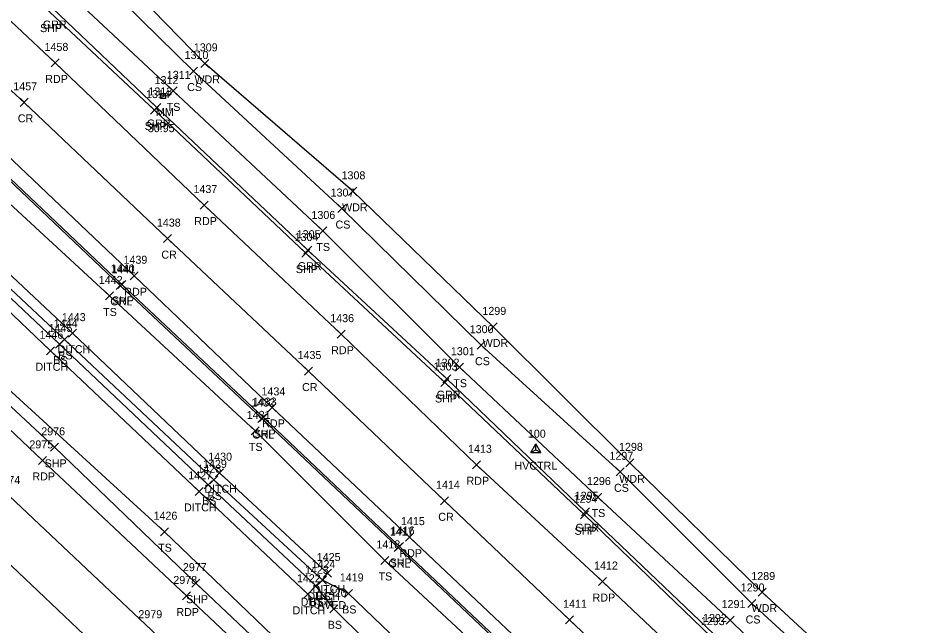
# Model space of a CAD drawing. Extents: x 1647574 to 1652703, y 212895 to 228670.
# Drawn here: x 1649361.4 to 1649589.7, y 226727.1 to 226878.8 of the extents above; entities that cross this region are included whole.
import ezdxf

# ---------------------------------------------------------------- set-up
doc = ezdxf.new("R2010")
doc.units = 0
for name, color, linetype in [('C_A', 7, 'Continuous'), ('C_I', 7, 'Continuous'), ('CPSM', 7, 'Continuous'), ('D_A', 7, 'Continuous'), ('D_C', 7, 'Continuous'), ('D_I', 7, 'Continuous'), ('D_TIC', 7, 'Continuous'), ('DD', 7, 'Continuous'), ('L_A', 7, 'Continuous'), ('L_I', 7, 'Continuous'), ('L_TIC', 7, 'Continuous'), ('LAWA', 7, 'Continuous'), ('LELB', 7, 'Continuous'), ('P_A', 7, 'Continuous'), ('P_I', 7, 'Continuous'), ('P_TIC', 7, 'Continuous'), ('PET', 7, 'Continuous'), ('PRC', 7, 'Continuous'), ('PSP', 7, 'Continuous'), ('R_A', 7, 'Continuous'), ('R_I', 7, 'Continuous'), ('R_TIC', 7, 'Continuous'), ('RGR', 7, 'Continuous'), ('S_A', 7, 'Continuous'), ('S_C', 7, 'Continuous'), ('S_I', 7, 'Continuous'), ('SRM', 7, 'Continuous')]:
    doc.layers.add(name, color=color, linetype=linetype)

msp = doc.modelspace()

# ---------------------------------------------------------------- linework, layer by layer
at = {"layer": 'CPSM'}
for p, q in [((1649489.45, 226770.32), (1649490.7, 226772.49)), ((1649491.95, 226770.32), (1649490.7, 226772.49)), ((1649490.7, 226771.04), (1649490.7, 226772.49)), ((1649489.45, 226770.32), (1649490.7, 226771.04)), ((1649489.45, 226770.32), (1649491.95, 226770.32)), ((1649490.7, 226771.04), (1649490.7, 226771.04)), ((1649490.7, 226771.04), (1649491.95, 226770.32))]:
    msp.add_line(p, q, dxfattribs=at)
at = {"layer": 'D_TIC'}
for points in [[(1649373.97, 226799.14), (1649375.97, 226801.14)], [(1649375.97, 226799.14), (1649373.97, 226801.14)], [(1649368.44, 226794.75), (1649370.44, 226796.75)], [(1649370.44, 226794.75), (1649368.44, 226796.75)], [(1649410.63, 226764.29), (1649412.63, 226766.29)], [(1649412.63, 226764.29), (1649410.63, 226766.29)], [(1649405.56, 226759.63), (1649407.56, 226761.63)], [(1649407.56, 226759.63), (1649405.56, 226761.63)], [(1649436.39, 226737.45), (1649438.39, 226739.45)], [(1649438.39, 226737.45), (1649436.39, 226739.45)], [(1649437.68, 226739.23), (1649439.68, 226741.23)], [(1649439.68, 226739.23), (1649437.68, 226741.23)], [(1649434.72, 226736.04), (1649436.72, 226738.04)], [(1649436.72, 226736.04), (1649434.72, 226738.04)], [(1649432.71, 226733.92), (1649434.71, 226735.92)], [(1649434.71, 226733.92), (1649432.71, 226735.92)], [(1649432.71, 226733.92), (1649434.71, 226735.92)], [(1649434.71, 226733.92), (1649432.71, 226735.92)]]:
    msp.add_lwpolyline(points, dxfattribs=at)
at = {"layer": 'DD'}
for points in [[(1649433.71, 226734.92), (1649406.56, 226760.63), (1649369.44, 226795.75), (1649333.75, 226829.67), (1649321.24, 226840.71), (1649314.05, 226849.25), (1649315.96, 226850.35), (1649317.41, 226851.47), (1649318.71, 226852.83)], [(1649433.71, 226734.92), (1649435.72, 226737.04), (1649437.39, 226738.45), (1649438.68, 226740.23), (1649411.63, 226765.29), (1649374.97, 226800.14), (1649337.85, 226834.87), (1649326.56, 226845.09), (1649318.71, 226852.83)]]:
    msp.add_lwpolyline(points, dxfattribs=at)
at = {"layer": 'L_TIC'}
for points in [[(1649407.03, 226866.53), (1649409.03, 226868.53)], [(1649409.03, 226866.53), (1649407.03, 226868.53)], [(1649404.15, 226864.62), (1649406.15, 226866.62)], [(1649406.15, 226864.62), (1649404.15, 226866.62)], [(1649399.06, 226859.66), (1649401.06, 226861.66)], [(1649401.06, 226859.66), (1649399.06, 226861.66)], [(1649443.95, 226834.57), (1649445.95, 226836.57)], [(1649445.95, 226834.57), (1649443.95, 226836.57)], [(1649441.21, 226830.27), (1649443.21, 226832.27)], [(1649443.21, 226830.27), (1649441.21, 226832.27)], [(1649436.47, 226824.67), (1649438.47, 226826.67)], [(1649438.47, 226824.67), (1649436.47, 226826.67)], [(1649383.19, 226808.44), (1649385.19, 226810.44)], [(1649385.19, 226808.44), (1649383.19, 226810.44)], [(1649479.07, 226800.7), (1649481.07, 226802.7)], [(1649481.07, 226800.7), (1649479.07, 226802.7)], [(1649371.93, 226797.59), (1649373.93, 226799.59)], [(1649373.93, 226797.59), (1649371.93, 226799.59)], [(1649370.65, 226796.42), (1649372.65, 226798.42)], [(1649372.65, 226796.42), (1649370.65, 226798.42)], [(1649476.06, 226796.14), (1649478.06, 226798.14)], [(1649478.06, 226796.14), (1649476.06, 226798.14)], [(1649470.69, 226790.64), (1649472.69, 226792.64)], [(1649472.69, 226790.64), (1649470.69, 226792.64)], [(1649419.61, 226774.73), (1649421.61, 226776.73)], [(1649421.61, 226774.73), (1649419.61, 226776.73)], [(1649513.21, 226766.75), (1649515.21, 226768.75)], [(1649515.21, 226766.75), (1649513.21, 226768.75)], [(1649510.82, 226764.51), (1649512.82, 226766.51)], [(1649512.82, 226764.51), (1649510.82, 226766.51)], [(1649407.87, 226761.28), (1649409.87, 226763.28)], [(1649409.87, 226761.28), (1649407.87, 226763.28)], [(1649409.25, 226762.49), (1649411.25, 226764.49)], [(1649411.25, 226762.49), (1649409.25, 226764.49)], [(1649505.26, 226758.21), (1649507.26, 226760.21)], [(1649507.26, 226758.21), (1649505.26, 226760.21)], [(1649396.93, 226749.55), (1649398.93, 226751.55)], [(1649398.93, 226749.55), (1649396.93, 226751.55)], [(1649452.02, 226742.38), (1649454.02, 226744.38)], [(1649454.02, 226742.38), (1649452.02, 226744.38)], [(1649436.39, 226737.45), (1649438.39, 226739.45)], [(1649438.39, 226737.45), (1649436.39, 226739.45)], [(1649434.72, 226736.04), (1649436.72, 226738.04)], [(1649436.72, 226736.04), (1649434.72, 226738.04)], [(1649442.87, 226734.13), (1649444.87, 226736.13)], [(1649444.87, 226734.13), (1649442.87, 226736.13)], [(1649546.28, 226734.48), (1649548.28, 226736.48)], [(1649548.28, 226734.48), (1649546.28, 226736.48)], [(1649543.7, 226731.63), (1649545.7, 226733.63)], [(1649545.7, 226731.63), (1649543.7, 226733.63)], [(1649439.27, 226730.3), (1649441.27, 226732.3)], [(1649441.27, 226730.3), (1649439.27, 226732.3)], [(1649538.29, 226727.48), (1649540.29, 226729.48)], [(1649540.29, 226727.48), (1649538.29, 226729.48)]]:
    msp.add_lwpolyline(points, dxfattribs=at)
at = {"layer": 'LAWA'}
msp.add_lwpolyline([(1649620.52, 226666.86), (1649581.67, 226703.66), (1649547.28, 226735.48), (1649514.21, 226767.75), (1649480.07, 226801.7), (1649444.95, 226835.57), (1649408.03, 226867.53), (1649382.09, 226894.12), (1649349.21, 226919.43), (1649317.07, 226948.87), (1649283.57, 226984.27), (1649262.7, 226991.58)], dxfattribs=at)
at = {"layer": 'LELB'}
for points in [[(1649601.72, 226556.3), (1649565.56, 226590.44), (1649531.93, 226623.52), (1649496.55, 226657.42), (1649463.01, 226688.13), (1649429.09, 226720.61), (1649397.93, 226750.55), (1649357.87, 226787.13), (1649324.24, 226819.11), (1649290.45, 226852.03), (1649264.6, 226876.99), (1649236.49, 226903.17), (1649212.26, 226932.02), (1649172.55, 226966.26), (1649148.69, 226987.13), (1649125.3, 227007.74), (1649116.81, 227012.43), (1649123.68, 227011.79), (1649139.12, 227006.12), (1649163.74, 226998.25), (1649180.85, 226995.42), (1649185.97, 226996.02), (1649188.1, 226997.43)], [(1649611.68, 226660.43), (1649573.8, 226694.76), (1649539.29, 226728.48), (1649506.26, 226759.21), (1649471.69, 226791.64), (1649437.47, 226825.67), (1649400.06, 226860.66), (1649373.97, 226885.13), (1649343.06, 226911.31), (1649307.79, 226942.26), (1649266.92, 226975.01), (1649262.13, 226979.91), (1649252.93, 226990.96)], [(1649593.12, 226613.01), (1649554.76, 226645.44), (1649523.05, 226677.15), (1649485.11, 226713.45), (1649453.02, 226743.38), (1649420.61, 226775.73), (1649384.19, 226809.44), (1649346.96, 226843.75), (1649308.84, 226878.4), (1649286.16, 226899.19), (1649254.43, 226924.59), (1649231.46, 226951.13), (1649215.58, 226955.64), (1649208.66, 226952.13), (1649203.07, 226945.74)], [(1649699.67, 226481.91), (1649679.45, 226501.99), (1649645.41, 226536.66), (1649612.61, 226568.57), (1649578.32, 226600.99), (1649543.98, 226632.95), (1649509.04, 226666.44), (1649473.07, 226698.81), (1649440.27, 226731.3), (1649435.72, 226737.04), (1649408.87, 226762.28), (1649371.65, 226797.42), (1649335.46, 226831.54), (1649323.17, 226842.84), (1649315.96, 226850.35), (1649312.9, 226852.88), (1649303.05, 226862.63), (1649272.9, 226885.04), (1649244.53, 226913.23), (1649219.14, 226937.73), (1649217.77, 226942.22), (1649215.75, 226944.46), (1649217.78, 226946.35), (1649219.53, 226943.85)], [(1650010.63, 226272.18), (1649976.36, 226308.87), (1649944.85, 226340.83), (1649916.6, 226368.96), (1649885.58, 226401.45), (1649851.41, 226433.71), (1649822.12, 226460.28), (1649782.98, 226498.9), (1649750.04, 226529.83), (1649718.83, 226559.66), (1649689.09, 226593.62), (1649652.01, 226632.5), (1649616.85, 226664.27), (1649578.69, 226701.52), (1649544.7, 226732.63), (1649511.82, 226765.51), (1649477.06, 226797.14), (1649442.21, 226831.27), (1649405.15, 226865.62), (1649378.95, 226891.41), (1649346.59, 226917.07), (1649311.19, 226946.22)], [(1649699.67, 226481.91), (1649706.82, 226489.3), (1649683.4, 226506.92), (1649648.98, 226540.18), (1649615.46, 226571.75), (1649582.54, 226604.31), (1649545.88, 226635.11), (1649514.99, 226670.75), (1649476.91, 226703.47), (1649443.87, 226735.13), (1649437.39, 226738.45), (1649410.25, 226763.49), (1649372.93, 226798.59), (1649336.35, 226832.76), (1649324.5, 226844.21), (1649317.41, 226851.47), (1649314.57, 226854.84), (1649305.82, 226864.42), (1649279.73, 226892.76), (1649248.17, 226918.18), (1649224.51, 226943.02), (1649219.53, 226943.85)]]:
    msp.add_lwpolyline(points, dxfattribs=at)
at = {"layer": 'P_TIC'}
for points in [[(1649369.63, 226866.64), (1649371.63, 226868.64)], [(1649371.63, 226866.64), (1649369.63, 226868.64)], [(1649361.82, 226856.8), (1649363.82, 226858.8)], [(1649363.82, 226856.8), (1649361.82, 226858.8)], [(1649394.45, 226854.86), (1649396.45, 226856.86)], [(1649396.45, 226854.86), (1649394.45, 226856.86)], [(1649406.87, 226831.14), (1649408.87, 226833.14)], [(1649408.87, 226831.14), (1649406.87, 226833.14)], [(1649397.71, 226822.76), (1649399.71, 226824.76)], [(1649399.71, 226822.76), (1649397.71, 226824.76)], [(1649432.22, 226819.15), (1649434.22, 226821.15)], [(1649434.22, 226819.15), (1649432.22, 226821.15)], [(1649389.38, 226813.48), (1649391.38, 226815.48)], [(1649391.38, 226813.48), (1649389.38, 226815.48)], [(1649386.28, 226811.32), (1649388.28, 226813.32)], [(1649388.28, 226811.32), (1649386.28, 226813.32)], [(1649441.1, 226798.89), (1649443.1, 226800.89)], [(1649443.1, 226798.89), (1649441.1, 226800.89)], [(1649432.88, 226789.68), (1649434.88, 226791.68)], [(1649434.88, 226789.68), (1649432.88, 226791.68)], [(1649466.98, 226786.83), (1649468.98, 226788.83)], [(1649468.98, 226786.83), (1649466.98, 226788.83)], [(1649423.85, 226780.6), (1649425.85, 226782.6)], [(1649425.85, 226780.6), (1649423.85, 226782.6)], [(1649421.68, 226778.06), (1649423.68, 226780.06)], [(1649423.68, 226778.06), (1649421.68, 226780.06)], [(1649369.43, 226770.63), (1649371.43, 226772.63)], [(1649371.43, 226770.63), (1649369.43, 226772.63)], [(1649366.41, 226767.36), (1649368.41, 226769.36)], [(1649368.41, 226767.36), (1649366.41, 226769.36)], [(1649474.91, 226766.27), (1649476.91, 226768.27)], [(1649476.91, 226766.27), (1649474.91, 226768.27)], [(1649466.9, 226757.27), (1649468.9, 226759.27)], [(1649468.9, 226757.27), (1649466.9, 226759.27)], [(1649501.87, 226753.78), (1649503.87, 226755.78)], [(1649503.87, 226753.78), (1649501.87, 226755.78)], [(1649458.14, 226748.19), (1649460.14, 226750.19)], [(1649460.14, 226748.19), (1649458.14, 226750.19)], [(1649455.66, 226745.86), (1649457.66, 226747.86)], [(1649457.66, 226745.86), (1649455.66, 226747.86)], [(1649404.77, 226736.7), (1649406.77, 226738.7)], [(1649406.77, 226736.7), (1649404.77, 226738.7)], [(1649506.42, 226737.11), (1649508.42, 226739.11)], [(1649508.42, 226737.11), (1649506.42, 226739.11)], [(1649402.39, 226733.5), (1649404.39, 226735.5)], [(1649404.39, 226733.5), (1649402.39, 226735.5)], [(1649498.1, 226727.54), (1649500.1, 226729.54)], [(1649500.1, 226727.54), (1649498.1, 226729.54)]]:
    msp.add_lwpolyline(points, dxfattribs=at)
at = {"layer": 'PET'}
for points in [[(1649049.09, 227034.42), (1649086.52, 226998.96), (1649109.21, 226977.52), (1649148.39, 226940.73), (1649176.97, 226913.97), (1649207.9, 226884.37), (1649242.38, 226852.27), (1649276.93, 226819.76), (1649310.57, 226787.99), (1649351.53, 226749.66), (1649386.03, 226717.08), (1649415.53, 226689.26), (1649446.48, 226660.42), (1649481.94, 226626.92), (1649519.05, 226591.95), (1649551.76, 226560.83), (1649585.69, 226528.77), (1649624.3, 226492.34)], [(1649093.95, 227025.5), (1649126.98, 226994.68), (1649165.92, 226958.16), (1649194.97, 226931.06), (1649223.59, 226903.58), (1649259.38, 226869.94), (1649293.46, 226837.81), (1649328.56, 226805.25), (1649367.41, 226768.36), (1649403.39, 226734.5), (1649427.73, 226711.63), (1649463.63, 226677.53), (1649497.38, 226645.66), (1649535.82, 226609.26), (1649568.76, 226578.15), (1649602.84, 226545.72)], [(1649598.45, 226617.55), (1649561.34, 226652.9), (1649529.43, 226682.64), (1649490.94, 226719.16), (1649459.14, 226749.19), (1649424.85, 226781.6), (1649390.38, 226814.48), (1649353.23, 226849.64), (1649316.21, 226884.71), (1649282.4, 226916.91), (1649254.37, 226943.23), (1649236.04, 226960.59), (1649216.52, 226978.85), (1649195.64, 226998.51)], [(1649615.14, 226636.4), (1649578.52, 226671.42), (1649547.96, 226699.81), (1649507.42, 226738.11), (1649475.91, 226767.27), (1649442.1, 226799.89), (1649407.87, 226832.14), (1649370.63, 226867.64), (1649333.42, 226902.59), (1649300.87, 226933.45), (1649271.58, 226961.22), (1649239.83, 226990.77)]]:
    msp.add_lwpolyline(points, dxfattribs=at)
at = {"layer": 'PRC'}
for points in [[(1649071, 227030.27), (1649097.26, 227005.13), (1649118.09, 226986.08), (1649157.01, 226949.33), (1649185.96, 226922.5), (1649216.08, 226894.13), (1649250.58, 226861.49), (1649285.59, 226828.84), (1649319.08, 226797.05), (1649359.19, 226759.47), (1649394.66, 226725.95), (1649419.6, 226702.04), (1649454.56, 226669.33), (1649489.14, 226637.08), (1649527.32, 226600.87), (1649559.91, 226569.96), (1649593.92, 226537.25)], [(1649606.75, 226626.95), (1649570.25, 226661.64), (1649538.47, 226691.38), (1649499.1, 226728.54), (1649467.9, 226758.27), (1649433.88, 226790.68), (1649398.71, 226823.76), (1649362.82, 226857.8), (1649324.19, 226893.36), (1649291.59, 226925.62), (1649262.78, 226952.36), (1649218.05, 226994.51)]]:
    msp.add_lwpolyline(points, dxfattribs=at)
at = {"layer": 'PSP'}
for points in [[(1649099.96, 227024.6), (1649112.12, 227013.19), (1649129.86, 226996.81), (1649168.15, 226960.9), (1649197.39, 226932.91), (1649226.27, 226906.09), (1649262.03, 226872.71), (1649296.02, 226840.81), (1649331.67, 226807.62), (1649370.43, 226771.63), (1649405.77, 226737.7), (1649429.96, 226714.79), (1649466.37, 226680.16), (1649499.94, 226648.68), (1649538.12, 226612.04), (1649571.18, 226581.28), (1649605.62, 226548.46)], [(1649595.64, 226615.02), (1649558.33, 226650.15), (1649527.09, 226680.38), (1649488.24, 226717.06), (1649456.66, 226746.86), (1649422.68, 226779.06), (1649387.28, 226812.32), (1649351.05, 226846.64), (1649313.21, 226882.31), (1649279.73, 226913.94), (1649251.2, 226941.22), (1649233.38, 226957.97), (1649213.56, 226976.76), (1649200.33, 226989.45), (1649199.76, 226990.72), (1649190.94, 226999.11)], [(1649606.95, 226655.87), (1649570.92, 226690.01), (1649534.66, 226724.21), (1649502.87, 226754.78), (1649467.98, 226787.83), (1649433.22, 226820.15), (1649395.45, 226855.86), (1649369.29, 226880.34), (1649338.69, 226908.03), (1649304.51, 226937.47), (1649274.58, 226964.09), (1649261.77, 226975.07), (1649262.11, 226976.25), (1649259.14, 226977.14), (1649257.68, 226977.62), (1649243.4, 226991.01), (1649239.83, 226990.77), (1649218.05, 226994.51), (1649195.64, 226998.51), (1649190.94, 226999.11)]]:
    msp.add_lwpolyline(points, dxfattribs=at)
at = {"layer": 'R_TIC'}
for points in [[(1649395.03, 226855.51), (1649397.03, 226857.51)], [(1649397.03, 226855.51), (1649395.03, 226857.51)], [(1649432.73, 226819.87), (1649434.73, 226821.87)], [(1649434.73, 226819.87), (1649432.73, 226821.87)], [(1649385.82, 226811.08), (1649387.82, 226813.08)], [(1649387.82, 226811.08), (1649385.82, 226813.08)], [(1649467.46, 226787.77), (1649469.46, 226789.77)], [(1649469.46, 226787.77), (1649467.46, 226789.77)], [(1649421.28, 226777.82), (1649423.28, 226779.82)], [(1649423.28, 226777.82), (1649421.28, 226779.82)], [(1649502.13, 226754.54), (1649504.13, 226756.54)], [(1649504.13, 226754.54), (1649502.13, 226756.54)], [(1649455.34, 226745.59), (1649457.34, 226747.59)], [(1649457.34, 226745.59), (1649455.34, 226747.59)]]:
    msp.add_lwpolyline(points, dxfattribs=at)
at = {"layer": 'RGR'}
for points in [[(1649553.69, 226650.38), (1649526.88, 226680.04), (1649487.89, 226716.68), (1649456.34, 226746.59), (1649422.28, 226778.82), (1649386.82, 226812.08), (1649350.56, 226846.46), (1649313.1, 226882.03), (1649279.45, 226913.72), (1649250.85, 226941.01), (1649232.6, 226957.18), (1649212.72, 226976.44), (1649200.04, 226988.83)], [(1649607.54, 226656.38), (1649571.29, 226690.65), (1649535.2, 226725), (1649503.13, 226755.54), (1649468.46, 226788.77), (1649433.73, 226820.87), (1649396.03, 226856.51), (1649370.04, 226881.22), (1649339.35, 226908.59), (1649304.93, 226938.03), (1649276.23, 226963.71), (1649262.11, 226976.25)]]:
    msp.add_lwpolyline(points, dxfattribs=at)
at = {"layer": 'SRM'}
msp.add_lwpolyline([(1649396.96, 226859.97), (1649398.21, 226859.97), (1649398.21, 226858.72), (1649396.96, 226858.72)], close=True, dxfattribs=at)
msp.add_circle((1649397.58, 226859.35), 0.0833, dxfattribs=at)

# ---------------------------------------------------------------- texts
at = {"layer": 'C_A'}
msp.add_text('HVCTRL', height=2, dxfattribs=at).set_placement((1649485.39, 226766.04))
at = {"layer": 'C_I'}
msp.add_text('100', height=2, dxfattribs=at).set_placement((1649488.74, 226774.04))
at = {"layer": 'D_A'}
for p in [(1649371.2, 226795.14), (1649365.67, 226790.75), (1649407.87, 226760.29), (1649402.79, 226755.63), (1649434.91, 226735.23), (1649433.62, 226733.45), (1649431.95, 226732.04), (1649429.94, 226729.92), (1649429.94, 226729.92)]:
    msp.add_text('DITCH', height=2, dxfattribs=at).set_placement(p)
at = {"layer": 'D_C'}
msp.add_text('PAVED', height=2, dxfattribs=at).set_placement((1649434.26, 226731.23))
at = {"layer": 'D_I'}
for s, p in [('1443', (1649372.27, 226803.14)), ('1446', (1649366.69, 226798.75)), ('1430', (1649408.85, 226768.29)), ('1427', (1649403.87, 226763.63)), ('1425', (1649435.98, 226743.23)), ('1423', (1649433.02, 226740.04)), ('1424', (1649434.7, 226741.45)), ('1422', (1649431.01, 226737.92)), ('1422', (1649431.01, 226737.92))]:
    msp.add_text(s, height=2, dxfattribs=at).set_placement(p)
at = {"layer": 'L_A'}
for s, p in [('WDR', (1649405.4, 226862.53)), ('CS', (1649403.59, 226860.62)), ('TS', (1649398.47, 226855.66)), ('WDR', (1649442.31, 226830.57)), ('CS', (1649440.66, 226826.27)), ('TS', (1649435.88, 226820.67)), ('TS', (1649382.6, 226804.44)), ('WDR', (1649477.43, 226796.7)), ('BS', (1649370.09, 226792.42)), ('BS', (1649371.37, 226793.59)), ('CS', (1649475.51, 226792.14)), ('TS', (1649470.1, 226786.64)), ('TS', (1649419.02, 226770.73)), ('WDR', (1649511.57, 226762.75)), ('CS', (1649510.26, 226760.51)), ('BS', (1649408.69, 226758.49)), ('BS', (1649407.31, 226757.28)), ('TS', (1649504.67, 226754.21)), ('TS', (1649396.34, 226745.55)), ('TS', (1649451.43, 226738.38)), ('BS', (1649435.83, 226733.45)), ('BS', (1649434.16, 226732.04)), ('BS', (1649442.32, 226730.13)), ('WDR', (1649544.64, 226730.48)), ('BS', (1649438.72, 226726.3)), ('CS', (1649543.15, 226727.63))]:
    msp.add_text(s, height=2, dxfattribs=at).set_placement(p)
at = {"layer": 'L_I'}
for s, p in [('1309', (1649405.25, 226870.53)), ('1310', (1649402.94, 226868.62)), ('1311', (1649398.5, 226863.66)), ('1308', (1649442.17, 226838.57)), ('1307', (1649439.44, 226834.27)), ('1306', (1649434.65, 226828.67)), ('1442', (1649381.5, 226812.44)), ('1299', (1649477.37, 226804.7)), ('1444', (1649370.24, 226801.59)), ('1445', (1649368.96, 226800.42)), ('1300', (1649474.21, 226800.14)), ('1301', (1649469.49, 226794.64)), ('1431', (1649418.48, 226778.73)), ('1298', (1649511.52, 226770.75)), ('1297', (1649509.13, 226768.51)), ('1428', (1649406.17, 226765.28)), ('1429', (1649407.55, 226766.49)), ('1296', (1649503.51, 226762.21)), ('1426', (1649395.19, 226753.55)), ('1418', (1649450.89, 226746.38)), ('1423', (1649433.02, 226740.04)), ('1424', (1649434.7, 226741.45)), ('1419', (1649441.74, 226738.13)), ('1289', (1649544.58, 226738.48)), ('1290', (1649541.93, 226735.63)), ('1420', (1649437.5, 226734.3)), ('1291', (1649537.16, 226731.48))]:
    msp.add_text(s, height=2, dxfattribs=at).set_placement(p)
at = {"layer": 'P_A'}
for s, p in [('SHP', (1649366.82, 226875.34)), ('RDP', (1649368.12, 226862.64)), ('CR', (1649361.26, 226852.8)), ('SHP', (1649392.98, 226850.86)), ('RDP', (1649405.36, 226827.14)), ('CR', (1649397.14, 226818.76)), ('SHP', (1649430.75, 226815.15)), ('RDP', (1649387.87, 226809.48)), ('SHP', (1649384.82, 226807.32)), ('RDP', (1649439.59, 226794.89)), ('CR', (1649432.31, 226785.68)), ('SHP', (1649465.52, 226782.83)), ('RDP', (1649422.34, 226776.6)), ('SHP', (1649420.21, 226774.06)), ('SHP', (1649367.97, 226766.63)), ('RDP', (1649364.9, 226763.36)), ('RDP', (1649473.4, 226762.27)), ('CR', (1649466.34, 226753.27)), ('SHP', (1649500.4, 226749.78)), ('RDP', (1649456.63, 226744.19)), ('SHP', (1649454.19, 226741.86)), ('RDP', (1649504.91, 226733.11)), ('SHP', (1649403.31, 226732.7)), ('RDP', (1649400.88, 226729.5))]:
    msp.add_text(s, height=2, dxfattribs=at).set_placement(p)
at = {"layer": 'P_I'}
for s, p in [('1458', (1649367.94, 226870.64)), ('1457', (1649360.13, 226860.8)), ('1314', (1649393.32, 226858.86)), ('1437', (1649405.17, 226835.14)), ('1438', (1649396.02, 226826.76)), ('1304', (1649430.45, 226823.15)), ('1439', (1649387.68, 226817.48)), ('1440', (1649384.5, 226815.32)), ('1436', (1649439.35, 226802.89)), ('1435', (1649431.18, 226793.68)), ('1303', (1649465.21, 226790.83)), ('1434', (1649422.16, 226784.6)), ('1433', (1649419.98, 226782.06)), ('2976', (1649367.12, 226774.63)), ('2975', (1649364.15, 226771.36)), ('1413', (1649473.78, 226770.27)), ('2974', (1649355.93, 226762.47)), ('1414', (1649465.78, 226761.27)), ('1294', (1649500.18, 226757.78)), ('1415', (1649457.02, 226752.19)), ('1416', (1649454.48, 226749.86)), ('2977', (1649402.51, 226740.7)), ('1412', (1649505.29, 226741.11)), ('2978', (1649400.13, 226737.5)), ('1411', (1649497.54, 226731.54)), ('2979', (1649391.4, 226728.95)), ('1293', (1649531.97, 226727.21))]:
    msp.add_text(s, height=2, dxfattribs=at).set_placement(p)
at = {"layer": 'R_A'}
for s, p in [('GRR', (1649367.52, 226876.22)), ('GRR', (1649393.52, 226851.51)), ('GRR', (1649431.22, 226815.87)), ('GRL', (1649384.37, 226807.08)), ('GRR', (1649465.95, 226783.77)), ('GRL', (1649419.83, 226773.82)), ('GRR', (1649500.62, 226750.54)), ('GRL', (1649453.88, 226741.59))]:
    msp.add_text(s, height=2, dxfattribs=at).set_placement(p)
at = {"layer": 'R_I'}
for s, p in [('1313', (1649393.9, 226859.51)), ('1305', (1649430.96, 226823.87)), ('1441', (1649384.7, 226815.08)), ('1302', (1649465.69, 226791.77)), ('1432', (1649419.59, 226781.82)), ('1295', (1649500.44, 226758.54)), ('1417', (1649454.21, 226749.59)), ('1292', (1649532.51, 226728))]:
    msp.add_text(s, height=2, dxfattribs=at).set_placement(p)
at = {"layer": 'S_A'}
msp.add_text('MM', height=2, dxfattribs=at).set_placement((1649395.77, 226854.35))
at = {"layer": 'S_C'}
msp.add_text('30.95', height=2, dxfattribs=at).set_placement((1649393.76, 226850.35))
at = {"layer": 'S_I'}
msp.add_text('1312', height=2, dxfattribs=at).set_placement((1649395.46, 226862.35))

doc.saveas('drawing.dxf')
